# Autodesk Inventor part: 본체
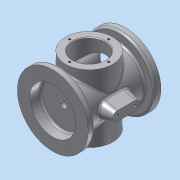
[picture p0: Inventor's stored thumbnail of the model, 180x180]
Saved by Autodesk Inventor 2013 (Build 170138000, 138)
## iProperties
Created: 2018-02
Part Number: 본체
Material: 알루미늄 6061
Document SubType Name: Modeling
Designer: Administrator
Density: 2.71 g/cm^3
Mass: 771.854 g
Surface Area: 821.859 cm^2
Volume: 284.817 cm^3
Author: Administrator
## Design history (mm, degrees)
sketch "스케치3"
  geometry: L1 (0, 54)-(0, -54); L2 (0, 54)-(52.5, 54); L3 (52.5, 54)-(52.5, 44); L4 (52.5, 44)-(38, 44); L5 (38, 44)-(38, -44); L6 (38, -44)-(52.5, -44); L7 (52.5, -44)-(52.5, -54); L8 (52.5, -54)-(0, -54); L9 (37, 54)-(37, 47); L10 (37, 47)-(33, 47); L11 (33, 47)-(33, -32); L12 (33, -32)-(5, -32); L13 (5, -32)-(5, -38); L14 (5, -38)-(34, -38); L15 (34, -38)-(34, -54); 2 further points
  constraints: 30 end point, 7 perpendicular, 5 parallel, 2 equal length, 2 point on line, 1 coincident, 1 collinear, 1 horizontal, 1 midpoint, 1 vertical
  dimensions: "d0" = 108 distance of L1.start L1.end; "d2" = 10 distance of L2.end L3.end; "d3" = 76 diameter of L5 L1; "d4" = 105 diameter of L7 L1; "d5" = 68 diameter of L15 L1; "d6" = 10 diameter of L13 L1; "d7" = 16 distance between parallel lines of L8 L14; "d8" = 79 distance between parallel lines of L10 L12; "d9" = 7 distance between parallel lines of L2 L10; "d10" = 74 diameter of L9 L1; "d11" = 66 diameter of L11 L1
revolve "회전1" sketch "스케치3" stored, may be unused: angle "d12" = 90 deg
fillet "모깎기1" dims "d13" = 3
chamfer "모따기1" distance "d14" = 1; stored, may be unused: second distance "d15" = 2, angle "d16" = 45 deg
node "작업 평면1"
sketch "스케치4"
  geometry: C1 r 35 at (0, 0); 1 further point
  constraints: 1 centre point, 1 coincident
  dimensions: "d18" = 70 diameter of C1
extrude "돌출1" join sketch "스케치4" stored distance "d19" = 10; taper "d20" = 0 deg
hole "구멍1" diameter "d23" = 48; stored, may be unused: countersink angle "d27" = 90 deg, drill point angle "d29" = 0 deg; dims "d21" = 10, "d22" = 10, "d24" = 6, "d25" = 4, "d26" = 2, "d28" = 8
sketch "스케치5"
  geometry: 2 further points
  constraints: 1 vertical alignment
  dimensions: "d30" = 29 distance of point (0, 29) point (0, 0)
hole "구멍2" sketch "스케치5" at (0, 29) diameter "d31" = 3.242; stored, may be unused: countersink angle "d35" = 90 deg, drill point angle "d37" = 118 deg; dims "d32" = 4, "d33" = 4, "d34" = 2, "d36" = 6
sketch "스케치6"
  geometry: 2 further points
  constraints: 1 vertical alignment
  dimensions: "d41" = 45 distance of point (0, 0) point (0, 45)
hole "구멍3" sketch "스케치6" at (0, 45) diameter "d42" = 3.242; stored, may be unused: countersink angle "d46" = 90 deg, drill point angle "d48" = 118 deg; dims "d43" = 4, "d44" = 4, "d45" = 2, "d47" = 6
node "작업 평면2"
sketch "스케치7"
  geometry: L1 (13, 7)-(-13, 7); L2 (13, -7)-(-13, -7); A1 r 7 centre (13, 0) between (13, -7) and (13, 7); A2 r 7 centre (-13, 0) between (-13, 7) and (-13, -7); 2 further points
  constraints: 4 end point, 4 point on circle, 4 tangent, 2 centre point, 1 horizontal alignment, 1 midpoint, 1 vertical alignment
  dimensions: "d53" = 14 diameter of A1; "d54" = 14 diameter of A2; "d55" = 40 dimension on A2 A1; "d56" = 13 distance of A2.centre point (0, 0)
extrude "돌출2" join sketch "스케치7" stored distance "d57" = 10; taper "d58" = 15 deg
sketch "스케치8"
  geometry: A1 r 7 centre (0, 13) between (7, 13) and (-7, 13) reference; A2 r 7 centre (0, -13) between (-7, -13) and (7, -13) reference; 3 further points
  constraints: 2 coincident
hole "구멍4" sketch "스케치8" at (0, 13), (0, -13) diameter "d59" = 4.134; stored, may be unused: countersink angle "d63" = 90 deg, drill point angle "d65" = 118 deg; dims "d60" = 6, "d61" = 4, "d62" = 2, "d64" = 8
fillet "모깎기2" dims "d66" = 3
sketch "스케치9"
  geometry: C1 r 43 at (0, 0); 1 further point
  constraints: 1 centre point, 1 coincident, 1 other
  dimensions: "d67" = 86 diameter of C1
feature "엠보싱1" sketch "스케치9" dims "d0" = 108, "d2" = 10, "d3" = 76, "d4" = 105, "d5" = 68, "d6" = 10, "d7" = 16, "d8" = 79, "d9" = 7, "d10" = 74, "d11" = 66, "d68" = 0.5, "d69" = 0
chamfer "모따기2" distance "d70" = 1; stored, may be unused: second distance "d71" = 2, angle "d72" = 45 deg
node "솔리드1"
pattern_circular "원형 패턴1" dims angle "d39" = 360 deg
mirror "대칭1"
pattern_circular "원형 패턴2" dims angle "d50" = 360 deg
other parameters: "d52" = 55
